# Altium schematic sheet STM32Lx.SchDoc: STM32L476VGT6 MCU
size A4; Date: 01-DEC-2013; Author: A.B; CompanyName: STMicroelectronics; Organization: Microcontrollers Division; Address1: 12, Rue Jules HOROWITZ; Address2: 38019 Grenoble; Address3: FRANCE; DocumentNumber: MB1184; Revision: C-01; SheetNumber: 3; SheetTotal: 10; Project: STM32L476G-DISCO
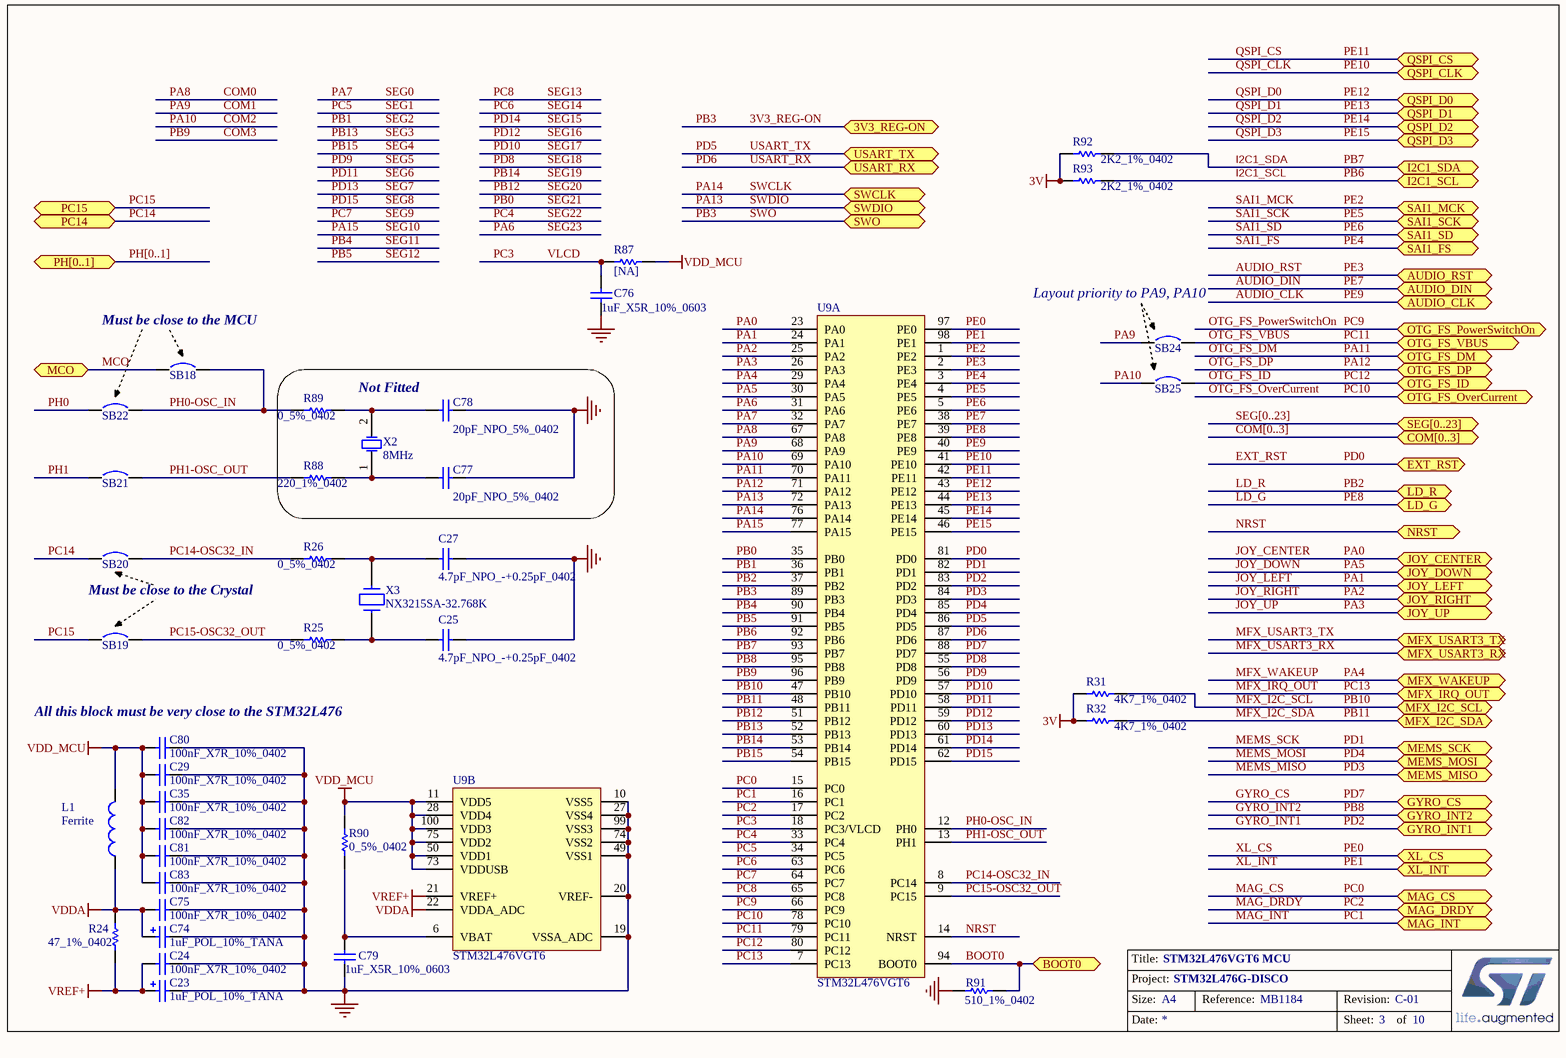
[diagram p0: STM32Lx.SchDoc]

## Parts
C23  1uF_POL_10%_TANA  [TAN-A]
C24  100nF_X7R_10%_0402  [0402C]
C25  4.7pF_NPO_-+0.25pF_0402  [0402C]
C27  4.7pF_NPO_-+0.25pF_0402  [0402C]
C29  100nF_X7R_10%_0402  [0402C]
C35  100nF_X7R_10%_0402  [0402C]
C74  1uF_POL_10%_TANA  [TAN-A]
C75  100nF_X7R_10%_0402  [0402C]
C76  1uF_X5R_10%_0603  [0603C]
C77  20pF_NPO_5%_0402  [0402C]
C78  20pF_NPO_5%_0402  [0402C]
C79  1uF_X5R_10%_0603  [0603C]
C80  100nF_X7R_10%_0402  [0402C]
C81  100nF_X7R_10%_0402  [0402C]
C82  100nF_X7R_10%_0402  [0402C]
C83  100nF_X7R_10%_0402  [0402C]
L1  Ferrite  [0603L]
R24  47_1%_0402  [0402R]
R25  0_5%_0402  [0402R]
R26  0_5%_0402  [0402R]
R31  4K7_1%_0402  [0402R]
R32  4K7_1%_0402  [0402R]
R87  [NA]  [0402R]
R88  220_1%_0402  [0402R]
R89  0_5%_0402  [0402R]
R90  0_5%_0402  [0402R]
R91  510_1%_0402  [0402R]
R92  2K2_1%_0402  [0402R]
R93  2K2_1%_0402  [0402R]
SB18  Circuit Breaker  [JP2_SMD]  (value not drawn)
SB19  Circuit Breaker  [JP2_SMD]  (value not drawn)
SB20  Circuit Breaker  [JP2_SMD]  (value not drawn)
SB21  Circuit Breaker  [JP2_SMD]  (value not drawn)
SB22  Circuit Breaker  [JP2_SMD]  (value not drawn)
SB24  Circuit Breaker  [JP2_SMD]  (value not drawn)
SB25  Circuit Breaker  [JP2_SMD]  (value not drawn)
U9  STM32L476VGT6  [TQFP100_14x14]  (parts A,B of 2)
X2  8MHz  [XTAL1]
X3  NX3215SA-32.768K  [XTAL_2SM_3R2X1R5]

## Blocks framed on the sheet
Not Fitted: C77 C78 R88 R89 X2

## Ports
3V3_REG-ON, AUDIO_CLK, AUDIO_DIN, AUDIO_RST, BOOT0, COM[0..3], EXT_RST, GYRO_CS, GYRO_INT1, GYRO_INT2, I2C1_SCL, I2C1_SDA, JOY_CENTER, JOY_DOWN, JOY_LEFT, JOY_RIGHT, JOY_UP, LD_G, LD_R, MAG_CS, MAG_DRDY, MAG_INT, MCO, MEMS_MISO, MEMS_MOSI, MEMS_SCK, MFX_I2C_SCL, MFX_I2C_SDA, MFX_IRQ_OUT, MFX_USART3_RX, MFX_USART3_TX, MFX_WAKEUP, NRST, OTG_FS_DM, OTG_FS_DP, OTG_FS_ID, OTG_FS_OverCurrent, OTG_FS_PowerSwitchOn, OTG_FS_VBUS, PC14, PC15, PH[0..1], QSPI_CLK, QSPI_CS, QSPI_D0, QSPI_D1, QSPI_D2 (bidir), QSPI_D3, SAI1_FS, SAI1_MCK, SAI1_SCK, SAI1_SD, SEG[0..23], SWCLK, SWDIO, SWO, USART_RX, USART_TX, XL_CS, XL_INT

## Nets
3V: R31.1 R32.1 R92.1 R93.1
GND: C23.2 C24.2 C25.2 C27.2 C29.2 C35.2 C74.2 C75.2 C76.1 C77.2 C78.2 C79.1 C80.2 C81.2 C82.2 C83.2 R91.1 U9.10(VSS5) U9.19(VSSA_ADC) U9.20(VREF-) U9.27(VSS4) U9.49(VSS1) U9.74(VSS2) U9.99(VSS3)
VDD_MCU: C29.1 C35.1 C80.1 C81.1 C82.1 C83.1 L1.2 R87.2 R90.2 U9.11(VDD5) U9.28(VDD4) U9.50(VDD1) U9.73(VDDUSB) U9.75(VDD2) U9.100(VDD3)
VDDA: C74.1 C75.1 L1.1 R24.2 U9.22(VDDA_ADC)
VREF+: C23.1 C24.1 R24.1 U9.21(VREF+)
3V3_REG-ON: U9.89(PB3) ; port SWO, port 3V3_REG-ON  [also labelled PB3, SWO]
AUDIO_CLK: U9.40(PE9) ; port AUDIO_CLK  [also labelled PE9]
AUDIO_DIN: U9.38(PE7) ; port AUDIO_DIN  [also labelled PE7]
AUDIO_RST: U9.2(PE3) ; port AUDIO_RST  [also labelled PE3]
BOOT0: R91.2 U9.94(BOOT0) ; port BOOT0
COM0: U9.67(PA8)  [also labelled PA8]
COM1: SB24.1 U9.68(PA9)  [also labelled PA9]
COM2: SB25.1 U9.69(PA10)  [also labelled PA10]
COM3: U9.96(PB9)  [also labelled PB9]
EXT_RST: U9.81(PD0) ; port EXT_RST  [also labelled PD0]
GYRO_CS: U9.88(PD7) ; port GYRO_CS  [also labelled PD7]
GYRO_INT1: U9.83(PD2) ; port GYRO_INT1  [also labelled PD2]
GYRO_INT2: U9.95(PB8) ; port GYRO_INT2  [also labelled PB8]
I2C1_SCL: R93.2 U9.92(PB6) ; port I2C1_SCL  [also labelled PB6]
I2C1_SDA: R92.2 U9.93(PB7) ; port I2C1_SDA  [also labelled PB7]
JOY_CENTER: U9.23(PA0) ; port JOY_CENTER  [also labelled PA0]
JOY_DOWN: U9.30(PA5) ; port JOY_DOWN  [also labelled PA5]
JOY_LEFT: U9.24(PA1) ; port JOY_LEFT  [also labelled PA1]
JOY_RIGHT: U9.25(PA2) ; port JOY_RIGHT  [also labelled PA2]
JOY_UP: U9.26(PA3) ; port JOY_UP  [also labelled PA3]
LD_G: U9.39(PE8) ; port LD_G  [also labelled PE8]
LD_R: U9.37(PB2) ; port LD_R  [also labelled PB2]
MAG_CS: U9.15(PC0) ; port MAG_CS  [also labelled PC0]
MAG_DRDY: U9.17(PC2) ; port MAG_DRDY  [also labelled PC2]
MAG_INT: U9.16(PC1) ; port MAG_INT  [also labelled PC1]
MCO: SB18.1 ; port MCO
MEMS_MISO: U9.84(PD3) ; port MEMS_MISO  [also labelled PD3]
MEMS_MOSI: U9.85(PD4) ; port MEMS_MOSI  [also labelled PD4]
MEMS_SCK: U9.82(PD1) ; port MEMS_SCK  [also labelled PD1]
MFX_I2C_SCL: R31.2 U9.47(PB10) ; port MFX_I2C_SCL  [also labelled PB10]
MFX_I2C_SDA: R32.2 U9.48(PB11) ; port MFX_I2C_SDA  [also labelled PB11]
MFX_IRQ_OUT: U9.7(PC13) ; port MFX_IRQ_OUT  [also labelled PC13]
MFX_WAKEUP: U9.29(PA4) ; port MFX_WAKEUP  [also labelled PA4]
NRST: U9.14(NRST) ; port NRST
OTG_FS_DM: U9.70(PA11) ; port OTG_FS_DM  [also labelled PA11]
OTG_FS_DP: U9.71(PA12) ; port OTG_FS_DP  [also labelled PA12]
OTG_FS_ID: SB25.2 U9.80(PC12) ; port OTG_FS_ID  [also labelled PC12]
OTG_FS_OverCurrent: U9.78(PC10) ; port OTG_FS_OverCurrent  [also labelled PC10]
OTG_FS_PowerSwitchOn: U9.66(PC9) ; port OTG_FS_PowerSwitchOn  [also labelled PC9]
OTG_FS_VBUS: SB24.2 U9.79(PC11) ; port OTG_FS_VBUS  [also labelled PC11]
PA6: U9.31(PA6)  [also labelled SEG23]
PA7: U9.32(PA7)  [also labelled SEG0]
PA13: U9.72(PA13) ; port SWDIO  [also labelled SWDIO]
PA14: U9.76(PA14) ; port SWCLK  [also labelled SWCLK]
PA15: U9.77(PA15)  [also labelled SEG10]
PB0: U9.35(PB0)  [also labelled SEG21]
PB1: U9.36(PB1)  [also labelled SEG2]
PB4: U9.90(PB4)  [also labelled SEG11]
PB5: U9.91(PB5)  [also labelled SEG12]
PB12: U9.51(PB12)  [also labelled SEG20]
PB13: U9.52(PB13)  [also labelled SEG3]
PB14: U9.53(PB14)  [also labelled SEG19]
PB15: U9.54(PB15)  [also labelled SEG4]
PC3: C76.2 R87.1 U9.18(PC3/VLCD)  [also labelled VLCD]
PC4: U9.33(PC4)  [also labelled SEG22]
PC5: U9.34(PC5)  [also labelled SEG1]
PC6: U9.63(PC6)  [also labelled SEG14]
PC7: U9.64(PC7)  [also labelled SEG9]
PC8: U9.65(PC8)  [also labelled SEG13]
PC14: SB20.1 ; port PC14
PC14-OSC32_IN: R26.1 SB20.2 U9.8(PC14)
PC15: SB19.1 ; port PC15
PC15-OSC32_OUT: R25.1 SB19.2 U9.9(PC15)
PD5: U9.86(PD5) ; port USART_TX  [also labelled USART_TX]
PD6: U9.87(PD6) ; port USART_RX  [also labelled USART_RX]
PD8: U9.55(PD8)  [also labelled SEG18]
PD9: U9.56(PD9)  [also labelled SEG5]
PD10: U9.57(PD10)  [also labelled SEG17]
PD11: U9.58(PD11)  [also labelled SEG6]
PD12: U9.59(PD12)  [also labelled SEG16]
PD13: U9.60(PD13)  [also labelled SEG7]
PD14: U9.61(PD14)  [also labelled SEG15]
PD15: U9.62(PD15)  [also labelled SEG8]
PE0: U9.97(PE0) ; port XL_CS  [also labelled XL_CS]
PE1: U9.98(PE1) ; port XL_INT  [also labelled XL_INT]
PE2: U9.1(PE2) ; port SAI1_MCK  [also labelled SAI1_MCK]
PE4: U9.3(PE4) ; port SAI1_FS  [also labelled SAI1_FS]
PE5: U9.4(PE5) ; port SAI1_SCK  [also labelled SAI1_SCK]
PE6: U9.5(PE6) ; port SAI1_SD  [also labelled SAI1_SD]
PE10: U9.41(PE10) ; port QSPI_CLK  [also labelled QSPI_CLK]
PE11: U9.42(PE11) ; port QSPI_CS  [also labelled QSPI_CS]
PE12: U9.43(PE12) ; port QSPI_D0  [also labelled QSPI_D0]
PE13: U9.44(PE13) ; port QSPI_D1  [also labelled QSPI_D1]
PE14: U9.45(PE14) ; port QSPI_D2  [also labelled QSPI_D2]
PE15: U9.46(PE15) ; port QSPI_D3  [also labelled QSPI_D3]
PH0: SB22.1
PH0-OSC_IN: R89.1 SB18.2 SB22.2 U9.12(PH0)
PH1: SB21.1
PH1-OSC_OUT: R88.1 SB21.2 U9.13(PH1)
NetC25_1: C25.1 R25.2 X3.2
NetC27_1: C27.1 R26.2 X3.1
NetC77_1: C77.1 R88.2 X2.1(OSC1)
NetC78_1: C78.1 R89.2 X2.2(OSC2)
NetC79_2: C79.2 R90.1 U9.6(VBAT)

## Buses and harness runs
bus COM[0..3] = port COM[0..3]
bus PH[0..1] = port PH[0..1]
bus SEG[0..23] = port SEG[0..23]

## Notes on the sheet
- (near SB24) Layout priority to PA9, PA10
- (near SB18) Must be close to the MCU
- Must be close to the Crystal
- (near C80) All this block must be very close to the STM32L476

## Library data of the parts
C23 C74 = Cap_1uF_POL_10%_TANA: Polarized Capacitor,1uF,16V,10%,typeA,AVX; Manuf_Part_1: TAJA105K016R
C24 C29 C35 C75 C80-C83 = Cap_100nF_X7R_10%_0402: Capacitor,100nF,16V,X7R,10%,0402,YAGEO; Manuf_Part_1: CC0402KRX7R7BB104
C25 C27 = Cap_4.7pF_NPO_-+0.25pF_0402: Capacitor, 4.7pF, 50V, NPO, -+0.25pF, 0402, YAGEO; Manuf_Part_1: CC0402CRNPO9BN4R7; Order: 311-1367-2-ND
C76 C79 = Cap_1uF_X5R_10%_0603: Capacitor,1uF,16V,X5R,10%,0603,YAGEO; Manuf_Part_1: CC0603KRX5R7BB105
C77 C78 = Cap_20pF_NPO_5%_0402: Capacitor,20pF,50V,NPO,5%,0402,YAGEO; Order: CC0402JRNPO9BN200; Fitted: NO
L1 = BEAD_600R_350MA_0603: Bead,600R,350mA,0603,FCM1608KF-601T03,Tai-tech; Manuf_2: TDK; Manuf_Part_2: MPZ1608S300A; Value: 100uH; Comment_1: bead,30R,5A,0603,MPZ1608S300A,TDK
R24 = Res_47_1%_0402: Resistor,47,0402,1%,YAGEO; Manuf_Part_1: RC0402FR-0747RL; Value: 47; Order: 311-47.0LRCT-ND
R25 R26 R90 = Res_0_5%_0402: Resistor,0,0402,5%,YAGEO; Manuf_Part_1: RC0402JR-070RL; Value: 0; Order: 2363467
R31 R32 = Res_4K7_1%_0402: Resistor,4K7,0402,1%,YAGEO; Manuf_Part_1: RT0402FRE074K7L
R87 = Res_NA_0402: Resistor,[NA],0402; Fitted: NO
R88 = Res_220_1%_0402: Resistor,220,0402,1%,YAGEO; Manuf_Part_1: RC0402FR-07220RL; Value: 220; Fitted: NO
R89 = Res_0_5%_0402: Resistor,0,0402,5%,YAGEO; Manuf_Part_1: RC0402JR-070RL; Value: 0; Order: 2363467; Fitted: NO
R91 = Res_510_1%_0402: Resistor,510,0402,1%,YAGEO; Manuf_Part_1: RC0402FR-07510L; Value: 510
R92 R93 = Res_2K2_1%_0402: Resistor,2K2,0402,1%,YAGEO; Manuf_Part_1: RC0402FR-072R2L
SB18-SB20 SB24 SB25 = Circuit Breaker: Solder: NO
SB21 SB22 = Circuit Breaker: Solder: YES
U9 = STM32L476VGT6: STM32 Orca (STM32L476VGT6); Manuf_Part_1: STM32L476VGT6U; Manuf_1: STM; Provided: ST; Ref St: xxxxxxxxx; ECCN_US/EU: 3A991A2/NEC
X2 = XTAL: Crystal Oscillator,8Mhz,20PF,20PPM,-10-70 degree,DIP,HC-49S; Manuf_Part_1: 9SL8000020AFXHF0; ECCN_US/EU: EAR99/NEC; Fitted: NO
X3 = XTAL_32K_NX3215SA: Crystal 32.768kHz, 6pF, -+20PPM, R=50K, SMD; Manuf_1: NDK; Manuf_Part_1: NX3215SA 32.768KHz EXS00A-MU00525; ECCN_US/EU: EAR99/NEC; Ref St: 9157034; NDK Ref: X3101802; Provided: ST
